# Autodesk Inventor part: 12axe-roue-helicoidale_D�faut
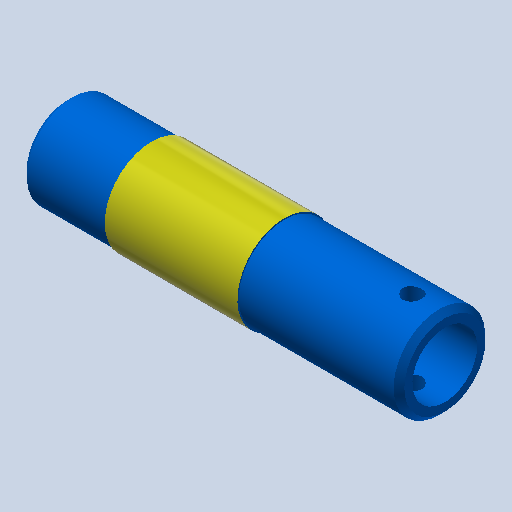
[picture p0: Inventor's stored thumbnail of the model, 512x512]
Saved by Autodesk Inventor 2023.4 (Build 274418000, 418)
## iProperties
Created: 2011-01
Part Number: 12axe-roue-helicoidale_D�faut
Document SubType Name: Modeling
Designer: eric
Density: 1 g/cm^3
Mass: 8.20486 g
Surface Area: 66.231 cm^2
Volume: 8.20486 cm^3
Material: Générique
Appearance: 0,128,255
Author: eric
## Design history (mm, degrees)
feature "Base1"
node "Corps solides"
node "Corps surfaciques"
node "Solide1"
